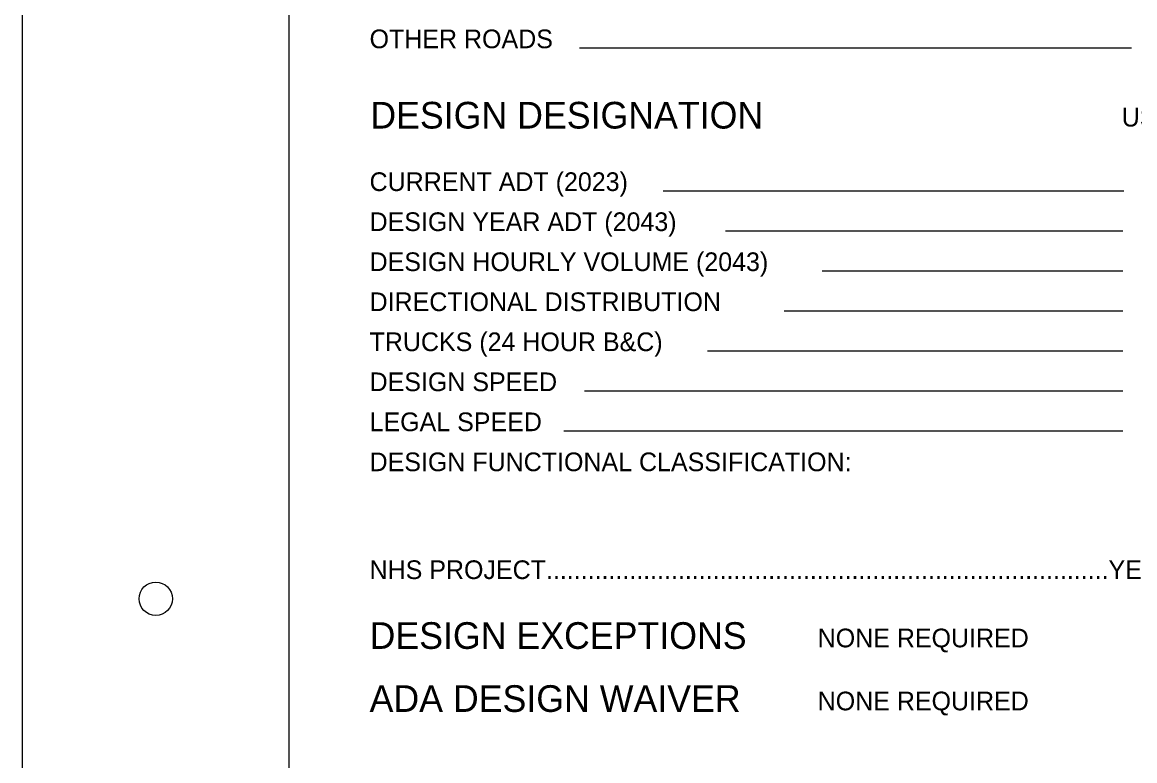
# Model space of a CAD drawing. Extents: x 39.5 to 73.5, y 15.6 to 37.6.
# Drawn here: x 39.5 to 47.83, y 21.14 to 26.67 of the extents above; entities that cross this region are included whole.
import ezdxf

# ---------------------------------------------------------------- set-up
doc = ezdxf.new("R2010")
doc.units = 0
for name, color, linetype in [('GM_X_City_Street', 7, 'Continuous'), ('GM_X_Hydro_Text', 7, 'Continuous'), ('GM_X_Interstate_Route', 7, 'Continuous'), ('GM_X_Major_River_Text', 7, 'Continuous')]:
    doc.layers.add(name, color=color, linetype=linetype)

msp = doc.modelspace()

# ---------------------------------------------------------------- linework, layer by layer
at = {"layer": 'GM_X_City_Street'}
msp.add_lwpolyline([(41.5012, 37.1011), (73.0012, 37.1011), (73.0012, 16.1011), (41.5012, 16.1011)], close=True, dxfattribs=at)
msp.add_circle((40.5012, 22.3511), 0.125, dxfattribs=at)
at = {"layer": 'GM_X_Hydro_Text'}
msp.add_lwpolyline([(39.5012, 15.6011), (73.5012, 15.6011), (73.5012, 37.6011), (39.5012, 37.6011)], close=True, dxfattribs=at)
at = {"layer": 'GM_X_Major_River_Text'}
for p, q in [((47.808, 26.4777), (43.6737, 26.4777)), ((47.7504, 25.4073), (44.3016, 25.4073)), ((47.7448, 25.1073), (44.7672, 25.1073)), ((47.7448, 24.8073), (45.4932, 24.8073)), ((47.7448, 24.5073), (45.2068, 24.5073)), ((47.7448, 24.2073), (44.6339, 24.2073)), ((47.7448, 23.9073), (43.7115, 23.9073)), ((47.7448, 23.6073), (43.5568, 23.6073))]:
    msp.add_line(p, q, dxfattribs=at)

# ---------------------------------------------------------------- texts
at = {"layer": 'GM_X_Interstate_Route'}
for s, height, p in [('OTHER ROADS', 0.14, (42.1024, 26.4777)), ('US-68 (S LEG)', 0.14, (47.7354, 25.891)), ('CURRENT ADT (2023)', 0.14, (42.1024, 25.4073)), ('DESIGN YEAR ADT (2043)', 0.14, (42.1024, 25.1073)), ('DESIGN HOURLY VOLUME (2043)', 0.14, (42.1024, 24.8073)), ('DIRECTIONAL DISTRIBUTION', 0.14, (42.1024, 24.5073)), ('TRUCKS (24 HOUR B&C)', 0.14, (42.1024, 24.2073)), ('DESIGN SPEED', 0.14, (42.1024, 23.9073)), ('LEGAL SPEED', 0.14, (42.1024, 23.6073)), ('DESIGN FUNCTIONAL CLASSIFICATION:', 0.14, (42.1024, 23.3073)), ('NHS PROJECT.................................................................................YES', 0.14, (42.1024, 22.4988)), ('DESIGN EXCEPTIONS', 0.2, (42.1024, 21.9755)), ('NONE REQUIRED', 0.14, (45.4584, 21.9872)), ('ADA DESIGN WAIVER', 0.2, (42.1024, 21.5031)), ('NONE REQUIRED', 0.14, (45.4584, 21.5149))]:
    msp.add_text(s, height=height, dxfattribs=at).set_placement(p)
at = {"layer": 'GM_X_Major_River_Text'}
msp.add_text('DESIGN DESIGNATION', height=0.2, dxfattribs=at).set_placement((42.108, 25.8757))

doc.saveas('drawing.dxf')
